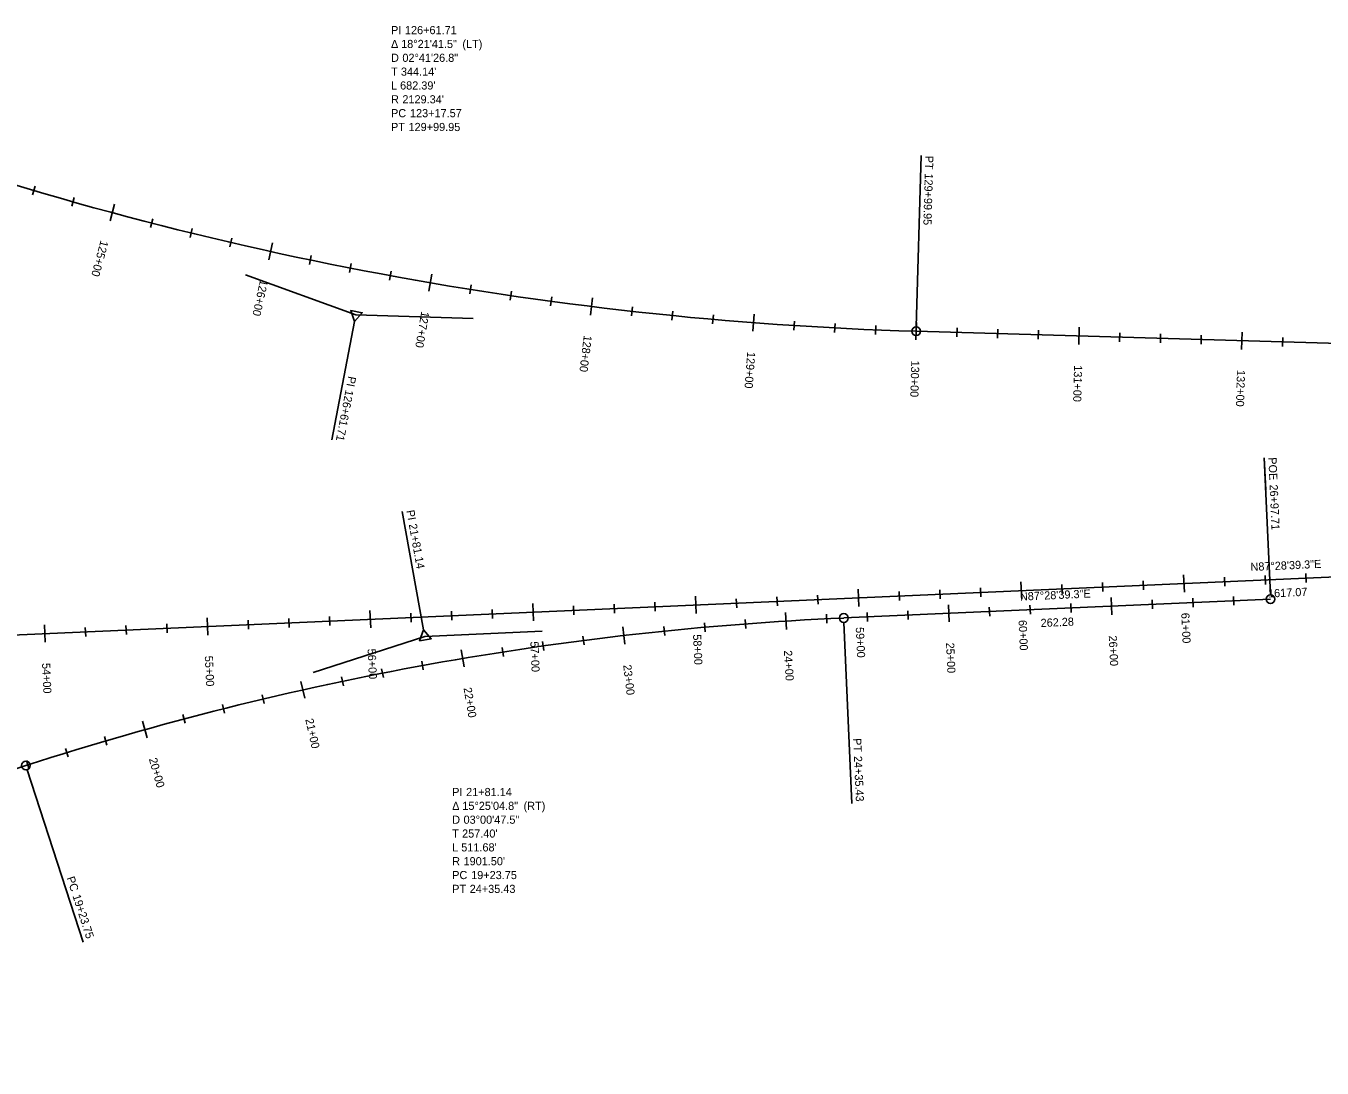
# Model space of a CAD drawing. Extents: x 2300830 to 2307917, y 756066 to 766359.
# Drawn here: x 2304246 to 2305042, y 760446 to 761086 of the extents above; entities that cross this region are included whole.
import ezdxf

# ---------------------------------------------------------------- set-up
doc = ezdxf.new("R2010")
doc.units = 0
for name, color, linetype in [('Default', 7, 'Continuous'), ('Draft_Bearing Label', 7, 'Continuous'), ('Draft_Curve Data Label', 7, 'Continuous'), ('Draft_Station Cardinal Lines', 7, 'Continuous'), ('Draft_Station Cardinal Points', 7, 'Continuous'), ('Draft_Station Labels Major', 7, 'Continuous'), ('Draft_Station Ticks Major', 7, 'Continuous'), ('Draft_Station Ticks Minor', 7, 'Continuous'), ('Geom_Baseline', 7, 'Continuous')]:
    doc.layers.add(name, color=color, linetype=linetype)

msp = doc.modelspace()

# ---------------------------------------------------------------- linework, layer by layer
at = {"layer": 'Default'}
for p, q in [((2304792.64, 760898.13), (2307906.67, 760807.43)), ((2304212.98, 760710.44), (2305828.49, 760781.61)), ((2304748.17, 760722.04), (2305010.2, 760733.58)), ((2303672.28, 760445.62), (2304246.15, 760631.42))]:
    msp.add_line(p, q, dxfattribs=at)
for centre, radius, start, end in [((2304854.63, 763026.57), 2129.34, 249.97011, 268.33163), ((2304831.86, 758822.38), 1901.5, 92.52241, 107.9404)]:
    msp.add_arc(centre, radius, start, end, dxfattribs=at)
at = {"layer": 'Draft_Station Cardinal Lines'}
for p, q in [((2304792.72, 760900.8), (2304795.78, 761006.09)), ((2304448.64, 760908.15), (2304380.99, 760932.81)), ((2304447.85, 760904.03), (2304433.96, 760831.55)), ((2304448.64, 760908.15), (2304520.61, 760906.06)), ((2304490.28, 760714.84), (2304477.17, 760787.47)), ((2304748.29, 760719.37), (2304753.19, 760608.15)), ((2304491.03, 760710.71), (2304422.53, 760688.53)), ((2304491.03, 760710.71), (2304562.96, 760713.88)), ((2304246.97, 760628.88), (2304281.26, 760522.97))]:
    msp.add_line(p, q, dxfattribs=at)
for points in [[(2304447.86, 760904.07), (2304452.57, 760909.52), (2304445.5, 760910.87)], [(2304490.29, 760714.8), (2304487.85, 760708.02), (2304494.94, 760709.3)]]:
    msp.add_lwpolyline(points, close=True, dxfattribs=at)
at = {"layer": 'Draft_Station Cardinal Points'}
for p, q in [((2304795.78, 761006.09), (2304795.78, 761006.09)), ((2304448.64, 760908.15), (2304448.64, 760908.15)), ((2304792.64, 760898.13), (2304792.64, 760898.13)), ((2304433.96, 760831.55), (2304433.96, 760831.55)), ((2305010.08, 760736.25), (2305006.37, 760820.5)), ((2305006.37, 760820.5), (2305007.23, 760800.83)), ((2304477.17, 760787.47), (2304477.17, 760787.47)), ((2305010.2, 760733.58), (2305010.2, 760733.58)), ((2304748.17, 760722.04), (2304748.17, 760722.04)), ((2304491.03, 760710.71), (2304491.03, 760710.71)), ((2304246.15, 760631.42), (2304246.15, 760631.42)), ((2304753.19, 760608.15), (2304753.19, 760608.15)), ((2304281.26, 760522.97), (2304281.26, 760522.97))]:
    msp.add_line(p, q, dxfattribs=at)
for centre in [(2304792.64, 760898.13), (2305010.2, 760733.58), (2304748.17, 760722.04), (2304246.15, 760631.42)]:
    msp.add_circle(centre, 2.67, dxfattribs=at)
at = {"layer": 'Draft_Station Ticks Major'}
for p, q in [((2304300.57, 760976.11), (2304297.8, 760965.86)), ((2304397.44, 760952.36), (2304395.16, 760941.99)), ((2304495.32, 760933.18), (2304493.52, 760922.72)), ((2304593.99, 760918.62), (2304592.69, 760908.08)), ((2304693.24, 760908.71), (2304692.43, 760898.12)), ((2304792.84, 760903.47), (2304792.53, 760892.85)), ((2304892.8, 760900.56), (2304892.49, 760889.94)), ((2304992.76, 760897.65), (2304992.45, 760887.03)), ((2304856.94, 760744.15), (2304857.41, 760733.54)), ((2304956.84, 760748.55), (2304957.31, 760737.94)), ((2304657.13, 760735.35), (2304657.6, 760724.74)), ((2304757.04, 760739.75), (2304757.5, 760729.14)), ((2304912.35, 760734.61), (2304912.82, 760724.01)), ((2304457.33, 760726.55), (2304457.79, 760715.94)), ((2304557.23, 760730.95), (2304557.7, 760720.34)), ((2304812.45, 760730.21), (2304812.91, 760719.6)), ((2304257.52, 760717.75), (2304257.99, 760707.14)), ((2304357.42, 760722.15), (2304357.89, 760711.54)), ((2304712.46, 760725.48), (2304713.13, 760714.88)), ((2304612.59, 760716.57), (2304613.81, 760706.02)), ((2304513.32, 760702.43), (2304515.1, 760691.95)), ((2304414.94, 760683.08), (2304417.26, 760672.72)), ((2304317.7, 760658.59), (2304320.57, 760648.37))]:
    msp.add_line(p, q, dxfattribs=at)
at = {"layer": 'Draft_Station Ticks Minor'}
for p, q in [((2304251.85, 760987.21), (2304250.28, 760981.91)), ((2304275.83, 760980.27), (2304274.33, 760974.96)), ((2304324.04, 760967.25), (2304322.66, 760961.9)), ((2304348.25, 760961.16), (2304346.94, 760955.8)), ((2304372.54, 760955.36), (2304371.28, 760949.98)), ((2304421.3, 760944.61), (2304420.17, 760939.2)), ((2304445.77, 760939.66), (2304444.71, 760934.25)), ((2304470.3, 760935.01), (2304469.3, 760929.58)), ((2304519.52, 760926.56), (2304518.65, 760921.11)), ((2304544.19, 760922.77), (2304543.39, 760917.31)), ((2304568.92, 760919.27), (2304568.17, 760913.8)), ((2304618.47, 760913.14), (2304617.86, 760907.66)), ((2304643.3, 760910.52), (2304642.75, 760905.02)), ((2304668.16, 760908.18), (2304667.67, 760902.68)), ((2304717.95, 760904.39), (2304717.59, 760898.88)), ((2304742.87, 760902.93), (2304742.58, 760897.42)), ((2304767.81, 760901.76), (2304767.59, 760896.25)), ((2304817.75, 760900.16), (2304817.59, 760894.64)), ((2304842.74, 760899.43), (2304842.58, 760893.92)), ((2304867.73, 760898.71), (2304867.57, 760893.19)), ((2304917.71, 760897.25), (2304917.55, 760891.73)), ((2304942.7, 760896.52), (2304942.54, 760891)), ((2304967.69, 760895.79), (2304967.53, 760890.28)), ((2305017.67, 760894.34), (2305017.51, 760888.82)), ((2304882.03, 760742.67), (2304882.27, 760737.16)), ((2304907, 760743.77), (2304907.25, 760738.26)), ((2304931.98, 760744.88), (2304932.22, 760739.36)), ((2304981.93, 760747.08), (2304982.17, 760741.56)), ((2305006.91, 760748.18), (2305007.15, 760742.66)), ((2305031.88, 760749.28), (2305032.13, 760743.76)), ((2304682.22, 760733.87), (2304682.46, 760728.36)), ((2304707.2, 760734.97), (2304707.44, 760729.46)), ((2304732.17, 760736.07), (2304732.42, 760730.56)), ((2304782.12, 760738.27), (2304782.37, 760732.76)), ((2304807.1, 760739.37), (2304807.34, 760733.86)), ((2304832.08, 760740.47), (2304832.32, 760734.96)), ((2304962.41, 760734.24), (2304962.66, 760728.72)), ((2304987.39, 760735.34), (2304987.63, 760729.82)), ((2304507.39, 760726.17), (2304507.63, 760720.66)), ((2304532.37, 760727.27), (2304532.61, 760721.76)), ((2304582.32, 760729.47), (2304582.56, 760723.96)), ((2304607.29, 760730.57), (2304607.54, 760725.06)), ((2304632.27, 760731.67), (2304632.51, 760726.16)), ((2304787.58, 760726.54), (2304787.83, 760721.02)), ((2304837.54, 760728.74), (2304837.78, 760723.22)), ((2304862.51, 760729.84), (2304862.75, 760724.32)), ((2304887.49, 760730.94), (2304887.73, 760725.42)), ((2304937.44, 760733.14), (2304937.68, 760727.62)), ((2304332.56, 760718.47), (2304332.8, 760712.95)), ((2304382.51, 760720.67), (2304382.76, 760715.15)), ((2304407.49, 760721.77), (2304407.73, 760716.26)), ((2304432.46, 760722.87), (2304432.71, 760717.36)), ((2304482.42, 760725.07), (2304482.66, 760719.56)), ((2304662.69, 760719.11), (2304663.19, 760713.61)), ((2304687.65, 760721.17), (2304688.06, 760715.67)), ((2304737.62, 760724.31), (2304737.89, 760718.79)), ((2304762.61, 760725.44), (2304762.85, 760719.92)), ((2304282.61, 760716.27), (2304282.85, 760710.75)), ((2304307.58, 760717.37), (2304307.83, 760711.85)), ((2304588.03, 760710.97), (2304588.74, 760705.49)), ((2304637.77, 760716.72), (2304638.34, 760711.23)), ((2304538.46, 760703.9), (2304539.31, 760698.45)), ((2304563.23, 760707.6), (2304564, 760702.13)), ((2304489.1, 760695.54), (2304490.09, 760690.11)), ((2304439.97, 760685.88), (2304441.1, 760680.48)), ((2304464.5, 760690.87), (2304465.56, 760685.45)), ((2304391.11, 760674.93), (2304392.38, 760669.56)), ((2304342.55, 760662.7), (2304343.97, 760657.37)), ((2304366.79, 760668.98), (2304368.14, 760663.62)), ((2304294.33, 760649.2), (2304295.89, 760643.9)), ((2304270.36, 760641.98), (2304271.99, 760636.7)), ((2304246.49, 760634.44), (2304248.19, 760629.18))]:
    msp.add_line(p, q, dxfattribs=at)
at = {"layer": 'Geom_Baseline'}
for p, q in [((2304792.64, 760898.13), (2307906.67, 760807.43)), ((2304212.98, 760710.44), (2305828.49, 760781.61)), ((2304748.17, 760722.04), (2305010.2, 760733.58)), ((2303672.28, 760445.62), (2304246.15, 760631.42))]:
    msp.add_line(p, q, dxfattribs=at)
for centre, radius, start, end in [((2304854.63, 763026.57), 2129.34, 249.97011, 268.33163), ((2304831.86, 758822.38), 1901.5, 92.52241, 107.9404)]:
    msp.add_arc(centre, radius, start, end, dxfattribs=at)

# ---------------------------------------------------------------- texts
at = {"layer": 'Draft_Bearing Label'}
for s, p in [('N87°28\'39.3"E', (2304997.97, 760750.9)), ('N87°28\'39.3"E', (2304856.42, 760732.69)), ('1617.07', (2305008.76, 760734.6)), ('262.28', (2304869.15, 760716.48))]:
    msp.add_text(s, height=5, rotation=2.52241, dxfattribs=at).set_placement(p)
at = {"layer": 'Draft_Curve Data Label'}
for s, p in [('PI ', (2304470.27, 761080.59)), ('126+61.71', (2304478.81, 761080.59)), ('Δ ', (2304470.27, 761072.09)), ('18°21\'41.5"', (2304476.49, 761072.09)), (' (LT)', (2304512.22, 761072.09)), ('D ', (2304470.27, 761063.59)), ('02°41\'26.8"', (2304477.25, 761063.59)), ('T ', (2304470.27, 761055.09)), ("344.14'", (2304476.35, 761055.09)), ('L ', (2304470.27, 761046.59)), ("682.39'", (2304475.83, 761046.59)), ('R ', (2304470.27, 761038.09)), ("2129.34'", (2304477.25, 761038.09)), ('PC ', (2304470.27, 761029.59)), ('123+17.57', (2304481.91, 761029.59)), ('PT ', (2304470.27, 761021.09)), ('129+99.95', (2304481.01, 761021.09)), ('PI ', (2304507.82, 760612.68)), ('21+81.14', (2304516.36, 760612.68)), ('Δ ', (2304507.82, 760604.18)), ('15°25\'04.8"', (2304514.04, 760604.18)), (' (RT)', (2304549.77, 760604.18)), ('D ', (2304507.82, 760595.68)), ('03°00\'47.5"', (2304514.8, 760595.68)), ('T ', (2304507.82, 760587.18)), ("257.40'", (2304513.9, 760587.18)), ('L ', (2304507.82, 760578.68)), ("511.68'", (2304513.38, 760578.68)), ('R ', (2304507.82, 760570.18)), ("1901.50'", (2304514.8, 760570.18)), ('PC ', (2304507.82, 760561.68)), ('19+23.75', (2304519.46, 760561.68)), ('PT ', (2304507.82, 760553.18)), ('24+35.43', (2304518.56, 760553.18))]:
    msp.add_text(s, height=5, dxfattribs=at).set_placement(p)
at = {"layer": 'Draft_Station Cardinal Points'}
for s, rotation, p in [('PT', 268.33163, (2304798.26, 761006.01)), ('129+99.95', 268.33163, (2304797.95, 760995.15)), ('PI ', 259.15087, (2304444.01, 760870.81)), ('126+61.71', 259.15087, (2304442.41, 760862.42)), ('POE ', 272.52241, (2305008.85, 760820.61)), ('26+97.71', 272.52241, (2305009.58, 760803.93)), ('PI ', 280.2314, (2304479.62, 760787.91)), ('21+81.14', 280.2314, (2304481.13, 760779.51)), ('PT', 272.52241, (2304753.92, 760648.09)), ('24+35.43', 272.52241, (2304754.4, 760637.23)), ('PC', 287.9404, (2304271.09, 760562.44)), ('19+23.75', 287.9404, (2304274.68, 760551.36))]:
    msp.add_text(s, height=5, rotation=rotation, dxfattribs=at).set_placement(p)
at = {"layer": 'Draft_Station Labels Major'}
for s, rotation, p in [('125+00', 254.87902, (2304292.07, 760954.23)), ('126+00', 257.5698, (2304389.98, 760930.1)), ('127+00', 260.26057, (2304488.91, 760910.6)), ('128+00', 262.95135, (2304588.65, 760895.77)), ('129+00', 265.64213, (2304688.97, 760885.63)), ('130+00', 268.33163, (2304789.66, 760880.21)), ('131+00', 268.33163, (2304889.62, 760877.3)), ('132+00', 268.33163, (2304989.58, 760874.39)), ('60+00', 272.52241, (2304855.47, 760720.72)), ('61+00', 272.52241, (2304955.37, 760725.13)), ('58+00', 272.52241, (2304655.66, 760711.92)), ('59+00', 272.52241, (2304755.56, 760716.32)), ('26+00', 272.52241, (2304910.88, 760711.19)), ('56+00', 272.52241, (2304455.86, 760703.12)), ('57+00', 272.52241, (2304555.76, 760707.52)), ('24+00', 273.59, (2304711.43, 760702.03)), ('25+00', 272.52241, (2304810.98, 760706.79)), ('54+00', 272.52241, (2304256.05, 760694.32)), ('55+00', 272.52241, (2304355.95, 760698.72)), ('23+00', 276.60319, (2304612.79, 760693.1)), ('22+00', 279.61638, (2304514.76, 760679)), ('21+00', 282.62957, (2304417.6, 760659.76)), ('20+00', 285.64276, (2304321.59, 760635.44))]:
    msp.add_text(s, height=5, rotation=rotation, dxfattribs=at).set_placement(p)

doc.saveas('drawing.dxf')
